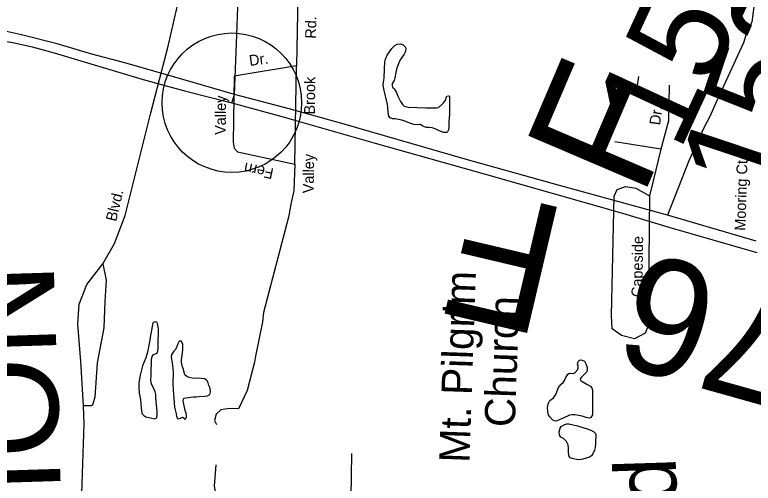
# Model space of a CAD drawing. Extents: x 2308163 to 2335412, y -96774 to 127732.
# Drawn here: x 2326312.3 to 2326403.4, y 123098.9 to 123156.8 of the extents above; entities that cross this region are included whole.
import ezdxf

# ---------------------------------------------------------------- set-up
doc = ezdxf.new("R2010")
doc.units = 0
for name, color, linetype in [('Default', 7, 'Continuous'), ('Old_Level_10', 7, 'Continuous'), ('Old_Level_22', 7, 'Continuous'), ('Old_Level_28', 7, 'Continuous'), ('Old_Level_32', 7, 'Continuous'), ('Old_Level_35', 7, 'Continuous'), ('Old_Level_60', 7, 'Continuous'), ('Old_Level_8', 7, 'Continuous'), ('Sheet Data Text CELL', 7, 'Continuous')]:
    doc.layers.add(name, color=color, linetype=linetype)

msp = doc.modelspace()

# ---------------------------------------------------------------- linework, layer by layer
at = {"layer": 'Default'}
msp.add_circle((2326339.084, 123145.898), 8.606, dxfattribs=at)
at = {"layer": 'Old_Level_28'}
for points in [[(2326339.409, 123146.896), (2326333.016, 123148.751), (2326325.851, 123150.821), (2326321.794, 123151.872), (2326317.527, 123153.145), (2326313.11, 123154.293), (2326310.521, 123154.856), (2326307.785, 123155.282), (2326305.324, 123155.414), (2326302.383, 123155.374), (2326299.428, 123154.954), (2326297.425, 123154.727), (2326290.327, 123153.553), (2326279.289, 123151.92), (2326272.885, 123151.072), (2326270.518, 123150.641)], [(2326270.573, 123149.548), (2326281.429, 123150.936), (2326293.6, 123152.794), (2326296.135, 123153.086), (2326300.764, 123153.818), (2326302.477, 123153.996), (2326305.324, 123154.04), (2326307.689, 123153.863), (2326310.194, 123153.635), (2326312.033, 123153.334), (2326314.432, 123152.778), (2326317.158, 123152.067), (2326328.124, 123148.747), (2326333.382, 123147.332), (2326339.084, 123145.898)], [(2326392.849, 123132.023), (2326379.524, 123135.697), (2326368.157, 123138.838), (2326352.664, 123143.354), (2326346.135, 123145.143), (2326339.409, 123146.896)], [(2326339.084, 123145.898), (2326345.248, 123144.178), (2326356.752, 123140.89), (2326370.231, 123137.108), (2326387.296, 123132.253), (2326393.022, 123130.539), (2326403.874, 123127.428)], [(2326403.82, 123128.796), (2326392.849, 123132.023)]]:
    msp.add_lwpolyline(points, dxfattribs=at)
at = {"layer": 'Old_Level_32'}
for points in [[(2326403.963, 123163.386), (2326403.942, 123162.13), (2326403.85, 123161.539), (2326403.905, 123160.47), (2326403.726, 123158.83), (2326403.495, 123157.436), (2326403.257, 123155.828), (2326402.83, 123154.959), (2326402.791, 123154.716), (2326402.567, 123154.419), (2326402.421, 123153.813), (2326402.224, 123153.306), (2326401.987, 123152.765), (2326398.861, 123145.959), (2326398.067, 123144.215), (2326397.346, 123142.804), (2326396.753, 123141.541), (2326395.494, 123138.713), (2326392.849, 123132.023)], [(2326339.409, 123146.896), (2326339.668, 123153.208), (2326339.863, 123158.853)], [(2326339.084, 123145.898), (2326339.409, 123146.896)]]:
    msp.add_lwpolyline(points, dxfattribs=at)
at = {"layer": 'Old_Level_35'}
msp.add_line((2326389.112, 123147.771), (2326389.302, 123149.148), dxfattribs=at)
for points in [[(2326324.709, 123077.648), (2326323.504, 123079.732), (2326322.674, 123080.356), (2326320.829, 123091.056), (2326320.671, 123093.869), (2326320.545, 123097.617), (2326320.844, 123106.286), (2326320.75, 123108.501), (2326320.427, 123113.958), (2326320.075, 123118.565), (2326320.245, 123121.026), (2326321.18, 123123.462), (2326323.142, 123126.032), (2326324.591, 123128.534), (2326325.902, 123131.978), (2326327.479, 123138.22), (2326329.063, 123144.632), (2326331.221, 123152.896), (2326333.028, 123160.831), (2326333.641, 123165.31)], [(2326347.285, 123161.311), (2326347.042, 123150.444), (2326339.378, 123149.177), (2326339.224, 123141.014), (2326339.369, 123140.286), (2326339.78, 123139.846), (2326346.837, 123138.326), (2326347.042, 123150.444)], [(2326393.045, 123148.074), (2326392.989, 123143.645), (2326392.049, 123140.157), (2326386.347, 123141.091)], [(2326392.049, 123140.157), (2326391.096, 123136.261), (2326390.622, 123134.394), (2326390.478, 123118.353), (2326390.12, 123117.465), (2326388.785, 123116.774), (2326387.16, 123117.158), (2326386.043, 123118.015), (2326385.935, 123119.656), (2326386.279, 123134.38), (2326386.635, 123135.186), (2326387.713, 123135.559), (2326388.934, 123135.353), (2326390.622, 123134.394)], [(2326346.837, 123138.326), (2326346.723, 123135.012), (2326346.418, 123133.576), (2326346.057, 123131.759), (2326342.97, 123120.021), (2326342.845, 123118.877), (2326342.017, 123114.609), (2326341.865, 123113.891), (2326340.978, 123110.39), (2326339.92, 123108.129), (2326338.772, 123108.169), (2326337.702, 123107.993), (2326337.13, 123107.46), (2326336.934, 123106.701), (2326337.171, 123106.182)], [(2326323.142, 123126.032), (2326323.583, 123123.991), (2326323.407, 123121.36), (2326323.296, 123118.13), (2326322.466, 123113.82), (2326322.149, 123109.576), (2326321.859, 123108.565), (2326321.686, 123108.486), (2326320.75, 123108.501)], [(2326353.46, 123075.346), (2326353.907, 123102.61)], [(2326337.085, 123101.216), (2326336.909, 123098.584), (2326337.334, 123096.102), (2326337.349, 123094.06), (2326337.091, 123091.516), (2326337.434, 123089.122), (2326338.1, 123086.206), (2326338.188, 123083.82), (2326337.848, 123081.365), (2326336.414, 123079.287), (2326334.773, 123076.161)]]:
    msp.add_lwpolyline(points, dxfattribs=at)
at = {"layer": 'Old_Level_60'}
for points in [[(2326365.928, 123144.5), (2326365.868, 123143.582), (2326365.855, 123142.856), (2326365.818, 123142.542), (2326365.71, 123142.302), (2326365.606, 123142.214), (2326365.243, 123142.242), (2326364.664, 123142.445), (2326364.18, 123142.659), (2326363.788, 123142.785), (2326363.392, 123142.859), (2326363.061, 123142.856), (2326362.644, 123143.017), (2326362.361, 123143.2), (2326361.989, 123143.182), (2326361.535, 123143.213), (2326361.038, 123143.367), (2326360.575, 123143.561), (2326360.045, 123143.737), (2326359.257, 123143.896), (2326358.912, 123143.898), (2326358.614, 123144.035), (2326358.452, 123144.234), (2326358.366, 123144.679), (2326358.331, 123145.315), (2326358.29, 123145.678), (2326357.983, 123147.091), (2326357.864, 123147.389), (2326357.739, 123148.085), (2326357.781, 123148.419), (2326357.902, 123148.928), (2326357.913, 123150.055), (2326357.98, 123150.942), (2326358.062, 123151.265), (2326358.267, 123151.781), (2326358.535, 123152.188), (2326358.837, 123152.584), (2326359.219, 123152.973), (2326359.502, 123153.12), (2326359.916, 123153.162), (2326360.218, 123153.055), (2326360.473, 123152.797), (2326360.557, 123152.647), (2326360.532, 123152.226), (2326360.348, 123151.892), (2326359.869, 123151.197), (2326359.676, 123150.802), (2326359.406, 123150.034), (2326359.311, 123149.646), (2326359.207, 123148.964), (2326359.108, 123148.637), (2326358.888, 123148.279), (2326358.857, 123147.97), (2326358.922, 123147.831), (2326359.139, 123147.605), (2326359.192, 123147.476), (2326359.374, 123147.226), (2326359.568, 123146.721), (2326359.912, 123146.033), (2326360.129, 123145.665), (2326360.368, 123145.459), (2326360.906, 123145.369), (2326363.006, 123145.261), (2326363.849, 123145.252), (2326364.365, 123145.265), (2326364.574, 123145.308), (2326364.995, 123145.66), (2326365.222, 123145.886), (2326365.457, 123146.228), (2326365.583, 123146.62), (2326365.633, 123146.715), (2326365.854, 123146.763), (2326365.933, 123146.694), (2326365.961, 123146.221), (2326365.967, 123145.906), (2326365.928, 123144.5)], [(2326329.874, 123107.401), (2326329.862, 123107.767), (2326329.724, 123109.012), (2326329.713, 123109.469), (2326329.683, 123109.887), (2326329.623, 123110.229), (2326329.5, 123110.523), (2326329.162, 123111.216), (2326329.088, 123111.62), (2326329.13, 123112.355), (2326329.165, 123114.193), (2326329.258, 123114.586), (2326329.427, 123114.845), (2326329.756, 123114.95), (2326329.882, 123115.078), (2326329.972, 123115.547), (2326329.973, 123116.31), (2326330.038, 123117.588), (2326330.03, 123117.903), (2326329.988, 123118.25), (2326329.902, 123118.649), (2326329.827, 123118.83), (2326329.598, 123118.863), (2326329.33, 123118.74), (2326329.078, 123117.397), (2326328.892, 123116.2), (2326328.674, 123115.104), (2326328.447, 123114.431), (2326328.067, 123113.428), (2326327.755, 123112.27), (2326327.626, 123111.594), (2326327.597, 123111.29), (2326327.593, 123110.874), (2326327.655, 123110.013), (2326327.787, 123109.266), (2326327.874, 123108.252), (2326327.971, 123107.563), (2326328.217, 123107.29), (2326328.479, 123107.144), (2326329.218, 123106.951), (2326329.57, 123106.903), (2326329.596, 123106.912), (2326329.817, 123107.011), (2326329.874, 123107.401)], [(2326336.444, 123110.223), (2326336.388, 123110.662), (2326336.245, 123110.992), (2326336.139, 123111.331), (2326336.044, 123111.573), (2326335.727, 123111.823), (2326335.302, 123111.868), (2326334.196, 123111.916), (2326333.82, 123111.97), (2326333.509, 123112.113), (2326333.262, 123112.314), (2326333.081, 123113.113), (2326332.935, 123113.433), (2326332.867, 123113.862), (2326332.861, 123114.167), (2326332.994, 123115.037), (2326333.024, 123115.427), (2326333.04, 123115.767), (2326333.024, 123116.062), (2326332.875, 123116.459), (2326332.595, 123116.478), (2326332.407, 123116.144), (2326332.294, 123115.828), (2326332.131, 123115.458), (2326331.903, 123115.222), (2326331.664, 123114.869), (2326331.578, 123114.577), (2326331.758, 123113.474), (2326331.829, 123112.648), (2326331.809, 123111.175), (2326331.823, 123110.474), (2326332.017, 123108.313), (2326332.196, 123107.488), (2326332.246, 123107.177), (2326332.425, 123106.881), (2326332.722, 123106.952), (2326332.98, 123107.075), (2326333.187, 123106.951), (2326333.26, 123106.827), (2326333.303, 123106.876), (2326333.461, 123107.048), (2326333.496, 123107.255), (2326333.43, 123107.578), (2326333.33, 123107.922), (2326333.067, 123109.12), (2326333.113, 123109.352), (2326333.206, 123109.45), (2326333.959, 123109.577), (2326334.339, 123109.589), (2326334.682, 123109.623), (2326335.009, 123109.627), (2326335.737, 123109.698), (2326336.082, 123109.747), (2326336.354, 123109.901), (2326336.444, 123110.223)], [(2326383.614, 123107.702), (2326383.587, 123107.388), (2326383.399, 123107.064), (2326383.24, 123106.983), (2326382.817, 123107.043), (2326382.312, 123107.208), (2326381.879, 123107.309), (2326381.438, 123107.37), (2326381.107, 123107.392), (2326380.771, 123107.353), (2326379.979, 123106.973), (2326379.493, 123106.777), (2326379.098, 123106.592), (2326378.904, 123106.624), (2326378.694, 123106.733), (2326378.324, 123107.127), (2326378.177, 123107.34), (2326378.083, 123107.791), (2326378.057, 123108.285), (2326378.114, 123108.704), (2326378.191, 123108.92), (2326378.338, 123109.134), (2326378.795, 123109.463), (2326379.057, 123109.876), (2326379.392, 123110.754), (2326379.744, 123111.168), (2326379.961, 123111.39), (2326380.139, 123111.602), (2326380.321, 123112.002), (2326380.563, 123112.421), (2326380.752, 123112.521), (2326381.236, 123112.489), (2326381.425, 123112.548), (2326381.74, 123112.934), (2326381.83, 123113.144), (2326381.849, 123113.382), (2326381.752, 123113.66), (2326381.858, 123114.012), (2326381.976, 123114.125), (2326382.2, 123114.158), (2326382.605, 123113.986), (2326382.802, 123113.614), (2326382.926, 123113.208), (2326382.927, 123112.878), (2326382.85, 123112.652), (2326382.239, 123112.027), (2326382.084, 123111.84), (2326382.117, 123111.676), (2326382.313, 123111.481), (2326382.837, 123111.224), (2326383.341, 123110.933), (2326383.529, 123110.718), (2326383.607, 123110.436), (2326383.614, 123107.702)], [(2326384.032, 123104.791), (2326383.963, 123104.102), (2326383.958, 123103.757), (2326383.925, 123103.357), (2326383.849, 123103.029), (2326383.623, 123102.554), (2326383.471, 123102.331), (2326383.234, 123102.176), (2326382.426, 123101.909), (2326382.015, 123101.817), (2326381.618, 123101.866), (2326381.255, 123101.955), (2326380.849, 123102.086), (2326380.718, 123102.233), (2326380.649, 123102.708), (2326380.641, 123103.246), (2326380.585, 123103.685), (2326380.381, 123104.073), (2326380.037, 123104.456), (2326379.709, 123104.63), (2326379.522, 123104.87), (2326379.499, 123105.303), (2326379.596, 123105.752), (2326379.732, 123105.945), (2326380.167, 123106.179), (2326380.415, 123106.278), (2326380.675, 123106.289), (2326381.756, 123106.038), (2326382.922, 123105.668), (2326383.377, 123105.494), (2326383.735, 123105.309), (2326384.001, 123105.021), (2326384.032, 123104.791)]]:
    msp.add_lwpolyline(points, dxfattribs=at)

# ---------------------------------------------------------------- texts
at = {"layer": 'Old_Level_10'}
for s, height, rotation, p in [('Rd.', 1.3328, 89.1148, (2326349.466, 123153.793)), ('Dr.', 1.3328, 7.31703, (2326341.295, 123150.433)), ('Brook', 1.3328, 89.11451, (2326349.321, 123144.43)), ('Valley', 1.3328, 89.34598, (2326338.319, 123141.92)), ('Dr.', 1.3328, 82.12929, (2326391.933, 123143.07)), ('Valley', 1.3328, 89.11338, (2326349.171, 123134.714)), ('Mooring Ct.', 1.33284, 88.26116, (2326402.471, 123130.086)), ('Fern', 1.3328, 167.80014, (2326344.327, 123137.761)), ('Blvd.', 1.3328, 76.55392, (2326324.791, 123131.166)), ('Capeside', 1.3328, 89.10122, (2326389.744, 123121.91))]:
    msp.add_text(s, height=height, rotation=rotation, dxfattribs=at).set_placement(p)
at = {"layer": 'Old_Level_22'}
for s, height, rotation, p in [('F', 15.994, 66.86767, (2326389.7, 123133.926)), ('F', 15.994, 166.72464, (2326380.904, 123132.643)), ('Mt. Pilgrim', 3.74861, 88.02472, (2326368.401, 123101.425)), ('Church', 3.7486, 88.02472, (2326374.012, 123105.821)), ('U.S. Coast Guard', 7.49722, 91.80479, (2326396.347, 123023.13))]:
    msp.add_text(s, height=height, rotation=rotation, dxfattribs=at).set_placement(p)
at = {"layer": 'Old_Level_8'}
for s, height, rotation, p in [('1528', 11.9955, 65.19909, (2326394.322, 123139.706)), ('1531', 11.9955, 71.48562, (2326405.398, 123133.621)), ('1576', 14.3947, 164.33815, (2326430.967, 123116.098))]:
    msp.add_text(s, height=height, rotation=rotation, dxfattribs=at).set_placement(p)
at = {"layer": 'Sheet Data Text CELL'}
msp.add_text('LOCATION', height=12, rotation=91.80479, dxfattribs=at).set_placement((2326319.661, 123044.272))

doc.saveas('drawing.dxf')
